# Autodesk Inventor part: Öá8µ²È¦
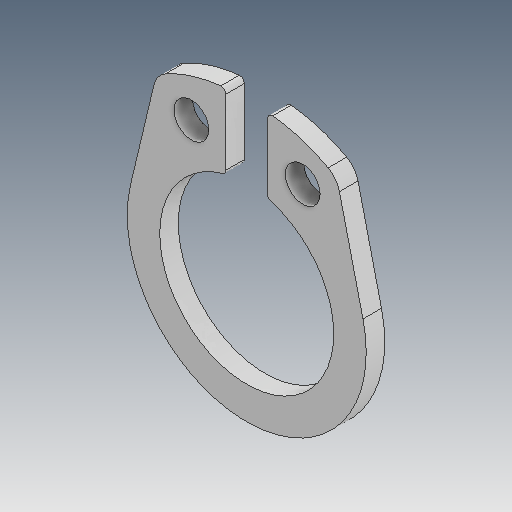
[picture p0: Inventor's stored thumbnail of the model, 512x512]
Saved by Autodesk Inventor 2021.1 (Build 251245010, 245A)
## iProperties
Created: 2019-04
Part Number: Öá8µ²È¦
Material: Ogólny
Document SubType Name: Modeling
Designer: user
Density: 1 g/cm^3
Appearance: Domyślna
Author: user
Revision Number: ÈÎºÎ
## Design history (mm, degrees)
feature "ÊäÈë1"
node "Bryła1"
